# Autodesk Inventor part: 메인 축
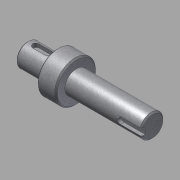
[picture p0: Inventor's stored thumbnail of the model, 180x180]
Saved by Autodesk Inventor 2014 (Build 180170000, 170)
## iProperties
Created: 2014-10
Part Number: 메인 축
Document SubType Name: Modeling
Designer: KYOUNG IL JANG
Density: 7.86 g/cm^3
Mass: 230.24 g
Surface Area: 74.3518 cm^2
Volume: 29.2926 cm^3
Material: 강철, 연강
Appearance: 금속-강(스테인리스, 브러시됨)
Author: SeoGD™ [www.esajin.kr]
Revision Number: 1
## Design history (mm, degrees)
sketch "스케치1"
  geometry: L1 (10.497, -57.5)-(102.497, -57.5); L2 (10.497, -66)-(32.497, -66); L3 (32.497, -72.5)-(46.5, -72.5); L4 (46.5, -66)-(102.497, -66); L5 (102.497, -66)-(102.497, -57.5); L6 (10.497, -66)-(10.497, -57.5); L7 (46.5, -69.749)-(46.5, -45.251) reference; L8 (46.5, -72.5)-(46.5, -66); L9 (32.497, -72.5)-(32.497, -66); L10 (32.497, -35)-(32.497, -80) reference; 2 further points
  constraints: 16 end point, 2 parallel, 2 perpendicular, 2 point on line, 1 collinear, 1 horizontal, 1 midpoint
  dimensions: "d0" = 17 diameter of L4 L1; "d1" = 30 diameter of L3 L1; "d2" = 22 distance of L2.start L2.end; "d3" = 55.99692 distance of L4.start L4.end (derived); "d5" = 17 diameter of L2 L1; "d19" = 70 distance between parallel lines of L5 L9
revolve "회전1" sketch "스케치1" stored, may be unused: angle "d4" = 90 deg
chamfer "모따기1" distance "d6" = 1; stored, may be unused: second distance "d7" = 2, angle "d8" = 45 deg
node "작업 평면1"
sketch "스케치2"
  geometry: L1 (-11, -7.5)-(-11, 7.5) reference; L2 (-4.5, 2.5)-(4.5, 2.5); L3 (4.5, -2.5)-(-4.5, -2.5); A1 r 2.5 centre (4.5, 0) between (4.5, -2.5) and (4.5, 2.5); A2 r 2.5 centre (-4.5, 0) between (-4.5, 2.5) and (-4.5, -2.5); 2 further points
  constraints: 4 end point, 4 point on circle, 4 tangent, 2 centre point, 1 horizontal alignment, 1 midpoint, 1 parallel, 1 perpendicular
  dimensions: "d9" = 5 distance between parallel lines of L3 L2; "d10" = 14 dimension on A1 A2; "d11" = 4 distance edge to line of A2 L1
extrude "돌출1" cut sketch "스케치2" distance "d12" = 3; taper "d13" = 0 deg
node "작업 평면2"
sketch "스케치3"
  geometry: L1 (27.998, 7.5)-(27.998, -7.5) reference; L2 (27.998, 2.5)-(12.498, 2.5); L3 (12.498, -2.5)-(27.998, -2.5); A1 r 2.5 centre (12.498, 0) between (12.498, 2.5) and (12.498, -2.5); 2 further points
  constraints: 4 end point, 2 perpendicular, 2 point on circle, 2 point on line, 2 tangent, 1 centre point, 1 horizontal alignment, 1 midpoint
  dimensions: "d14" = 5 distance between parallel lines of L3 L2; "d15" = 18 dimension on A1 L1
extrude "돌출2" cut sketch "스케치3" distance "d16" = 3; taper "d17" = 0 deg
node "솔리드1"
node "참조4"
node "참조5"
